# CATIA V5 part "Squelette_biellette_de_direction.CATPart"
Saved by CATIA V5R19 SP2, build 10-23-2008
Part number: squelette_biellette_de_direction
Bounding box of the stored display mesh (mm): x 0 to 200, y -770 to -680, z 0 to 0
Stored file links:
  C:\Users\Pauline\Desktop\CFAO_Catia\Compte_rendu\pmayet_assemblage_animation4\Squelette_biellette_de_direction.CATPart
  C:\Users\Pauline\Desktop\CFAO_Catia\Compte_rendu\pmayet_assemblage_animation4\pmayet_assemblage_animation.CATProduct
  C:\Users\Pauline\Desktop\Projet Catia\Assemblage\Part3.CATPart
  C:\Users\Pauline\Desktop\CFAO_Catia\Compte_rendu\pmayet_assemblage_animation4\Squelette_de_base.CATPart
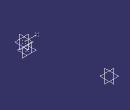
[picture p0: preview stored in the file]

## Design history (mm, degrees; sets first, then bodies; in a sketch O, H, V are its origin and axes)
Set1
  Point1: linked copy from another document
  Point2: linked copy from another document
  Plane1: linked copy from another document
  Point3: linked copy from another document
  Plane2: linked copy from another document
Set2
  Line1: type PtPt, FirstPoint Point1, SecondPoint Point2
  Plane3: type OffsetPt, RefPlane xy-plane, RefPoint Point1
  Plane4: type OffsetPt, RefPlane yz-plane, RefPoint Point1
  Plane5: type OffsetPt, RefPlane zx-plane, RefPoint Point1
  Plane6: type OffsetPt, RefPlane Plane1, RefPoint Point3
  Plane7: type OffsetPt, RefPlane Plane2, RefPoint Point3
Body1 (main body)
